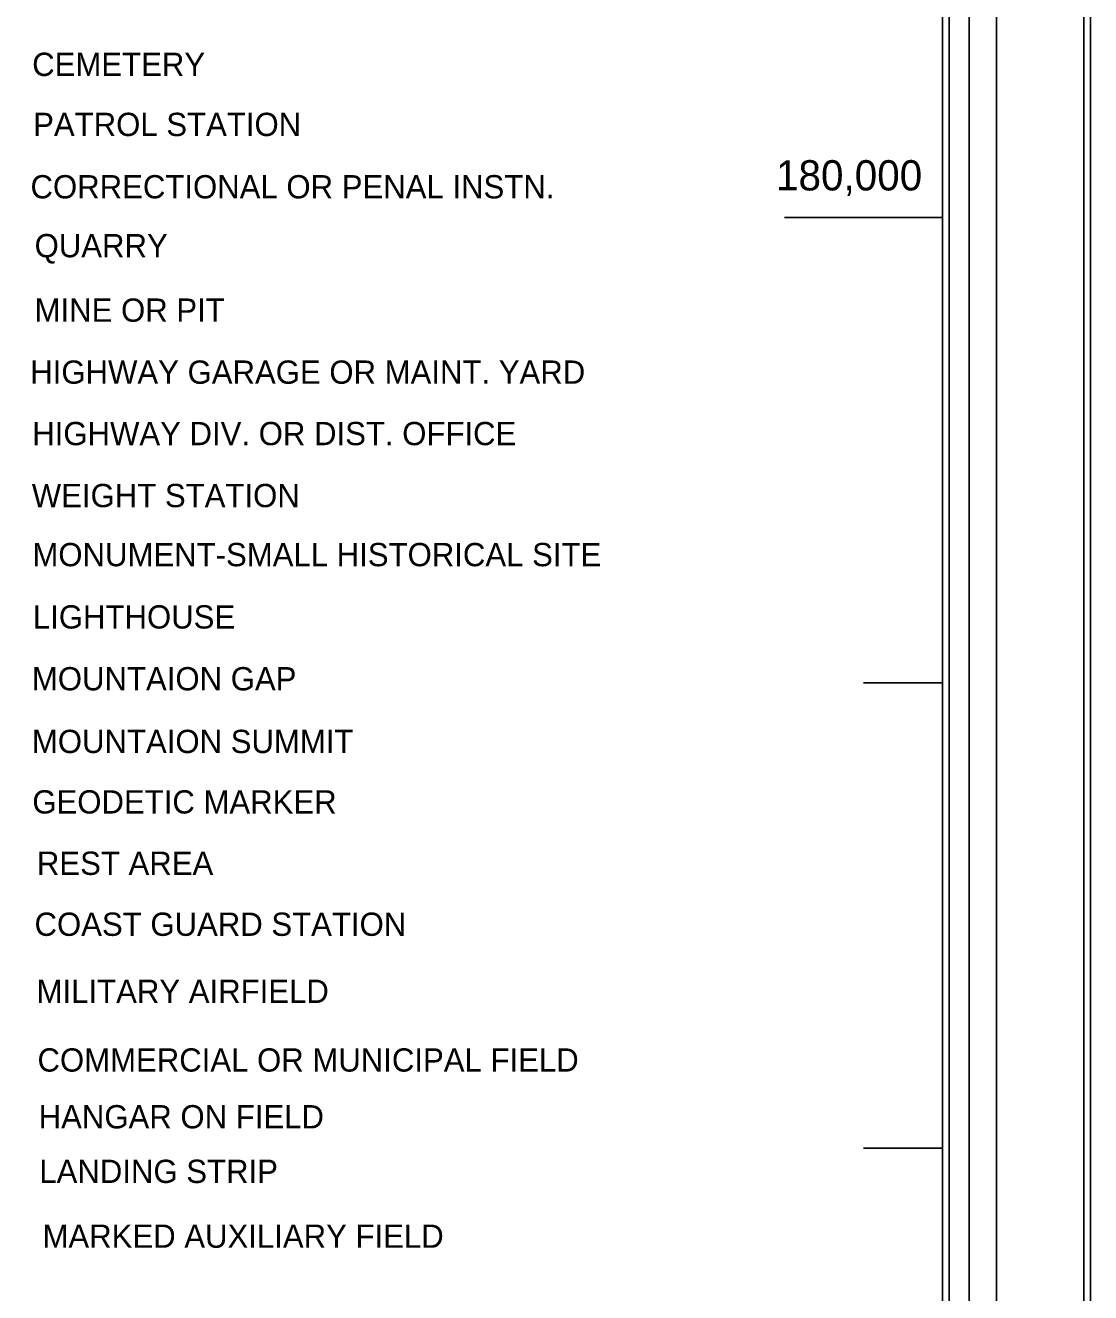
# Model space of a CAD drawing. Extents: x 5197761 to 5514561, y 1890130 to 2080942.
# Drawn here: x 5491672 to 5514561, y 1958318 to 1985551 of the extents above; entities that cross this region are included whole.
import ezdxf

# ---------------------------------------------------------------- set-up
doc = ezdxf.new("R2010")
doc.units = 0
for name, color, linetype in [('Exist Aviation Coast Guard Station Label', 7, 'Continuous'), ('Exist Aviation Commercial or Municipal Label', 7, 'Continuous'), ('Exist Aviation Field Marked Auxiliary Label', 7, 'Continuous'), ('Exist Aviation Hanger Label', 7, 'Continuous'), ('Exist Aviation Military Label', 7, 'Continuous'), ('Exist Aviation Public Landing Strip Label', 7, 'Continuous'), ('Exist Civil Correctional or Penal Institution Label', 7, 'Continuous'), ('Exist Civil NCDOT Division Office Label', 7, 'Continuous'), ('Exist Civil NCDOT Garage or Maintenance Office Label', 7, 'Continuous'), ('Exist Civil Patrol Station Label', 7, 'Continuous'), ('Exist Cultural Cemetery Label', 7, 'Continuous'), ('Exist Cultural Historical Site Label', 7, 'Continuous'), ('Exist Cultural Lighthouse Label', 7, 'Continuous'), ('Exist Cultural Weight Station Label', 7, 'Continuous'), ('Exist Geographical Mine Shaft Label', 7, 'Continuous'), ('Exist Geographical Mountain Gap Label', 7, 'Continuous'), ('Exist Geographical Mountain Summit Label', 7, 'Continuous'), ('Exist Geographical Quarry Label', 7, 'Continuous'), ('Exist Road Primary Interstate Rest Area Label', 7, 'Continuous'), ('Exist Survey Geodetic Marker Label', 7, 'Continuous'), ('Map Preparation Base StatePlane Tick Label', 7, 'Continuous'), ('Map Preparation Base StatePlane Tick Mark', 7, 'Continuous'), ('Map Preparation Border Antique Large Shape', 7, 'Continuous'), ('Map Preparation Border Antique Small Shape', 7, 'Continuous'), ('Map Preparation Border Black Inside Shape', 7, 'Continuous'), ('Map Preparation Border Black Middle Shape', 7, 'Continuous'), ('Map Preparation Border Black Outside Shape', 7, 'Continuous')]:
    doc.layers.add(name, color=color, linetype=linetype)

msp = doc.modelspace()

# ---------------------------------------------------------------- linework, layer by layer
at = {"layer": 'Map Preparation Base StatePlane Tick Mark'}
for p, q in [((5507980, 1981420), (5511378, 1981420)), ((5509679, 1971420), (5511378, 1971420)), ((5509679, 1961420), (5511378, 1961420))]:
    msp.add_line(p, q, dxfattribs=at)
at = {"layer": 'Map Preparation Border Antique Large Shape'}
msp.add_lwpolyline([(5197907, 2074783), (5207205, 2074783), (5207205, 1892697), (5512539, 1892697), (5512539, 2072359), (5207205, 2072359), (5207205, 2074783), (5514414, 2074783), (5514414, 1890276), (5197907, 1890276)], close=True, dxfattribs=at)
at = {"layer": 'Map Preparation Border Antique Small Shape'}
msp.add_lwpolyline([(5207791, 2071720), (5208220, 2071720), (5208220, 1893712), (5511524, 1893712), (5511524, 2071291), (5208220, 2071291), (5208220, 2071720), (5207791, 2071720), (5511953, 2071720), (5511953, 1893283), (5208220, 1893283), (5207791, 1893283)], close=True, dxfattribs=at)
at = {"layer": 'Map Preparation Border Black Inside Shape'}
msp.add_lwpolyline([(5208220, 2071291), (5511524, 2071291), (5511524, 1893712), (5208366, 1893712), (5208366, 1893858), (5511378, 1893858), (5511378, 2071145), (5208366, 2071145), (5208366, 1893858), (5208366, 1893712), (5208220, 1893712), (5208220, 1893858)], close=True, dxfattribs=at)
at = {"layer": 'Map Preparation Border Black Middle Shape'}
msp.add_lwpolyline([(5207205, 2072359), (5512539, 2072359), (5512539, 1892697), (5511953, 1892697), (5207791, 1892697), (5207791, 1893283), (5511953, 1893283), (5511953, 2071720), (5207791, 2071720), (5207791, 1892697), (5207205, 1892697)], close=True, dxfattribs=at)
at = {"layer": 'Map Preparation Border Black Outside Shape'}
msp.add_lwpolyline([(5197761, 2074930), (5514561, 2074930), (5514561, 1890130), (5197907, 1890130), (5197907, 1890276), (5514414, 1890276), (5514414, 2074783), (5197907, 2074783), (5197907, 1890130), (5197761, 1890130)], close=True, dxfattribs=at)

# ---------------------------------------------------------------- texts
at = {"layer": 'Exist Aviation Coast Guard Station Label'}
msp.add_text('COAST GUARD STATION', height=500, dxfattribs=at).set_placement((5491869, 1965985))
at = {"layer": 'Exist Aviation Commercial or Municipal Label'}
msp.add_text('COMMERCIAL OR MUNICIPAL FIELD', height=500, dxfattribs=at).set_placement((5491933, 1963068))
at = {"layer": 'Exist Aviation Field Marked Auxiliary Label'}
msp.add_text('MARKED AUXILIARY FIELD', height=500, dxfattribs=at).set_placement((5492041, 1959282))
at = {"layer": 'Exist Aviation Hanger Label'}
msp.add_text('HANGAR ON FIELD', height=500, dxfattribs=at).set_placement((5491958, 1961848))
at = {"layer": 'Exist Aviation Military Label'}
msp.add_text('MILITARY AIRFIELD', height=500, dxfattribs=at).set_placement((5491914, 1964544))
at = {"layer": 'Exist Aviation Public Landing Strip Label'}
msp.add_text('LANDING STRIP', height=500, dxfattribs=at).set_placement((5491972, 1960675))
at = {"layer": 'Exist Civil Correctional or Penal Institution Label'}
msp.add_text('CORRECTIONAL OR PENAL INSTN.', height=500, dxfattribs=at).set_placement((5491783, 1981832))
at = {"layer": 'Exist Civil NCDOT Division Office Label'}
msp.add_text('HIGHWAY DIV. OR DIST. OFFICE', height=500, dxfattribs=at).set_placement((5491820, 1976529))
at = {"layer": 'Exist Civil NCDOT Garage or Maintenance Office Label'}
msp.add_text('HIGHWAY GARAGE OR MAINT. YARD', height=500, dxfattribs=at).set_placement((5491777, 1977849))
at = {"layer": 'Exist Civil Patrol Station Label'}
msp.add_text('PATROL STATION', height=500, dxfattribs=at).set_placement((5491840, 1983172))
at = {"layer": 'Exist Cultural Cemetery Label'}
msp.add_text('CEMETERY', height=500, dxfattribs=at).set_placement((5491819, 1984463))
at = {"layer": 'Exist Cultural Historical Site Label'}
msp.add_text('MONUMENT-SMALL HISTORICAL SITE', height=500, dxfattribs=at).set_placement((5491824, 1973928))
at = {"layer": 'Exist Cultural Lighthouse Label'}
msp.add_text('LIGHTHOUSE', height=500, dxfattribs=at).set_placement((5491834, 1972589))
at = {"layer": 'Exist Cultural Weight Station Label'}
msp.add_text('WEIGHT STATION', height=500, dxfattribs=at).set_placement((5491811, 1975197))
at = {"layer": 'Exist Geographical Mine Shaft Label'}
msp.add_text('MINE OR PIT', height=500, dxfattribs=at).set_placement((5491871, 1979181))
at = {"layer": 'Exist Geographical Mountain Gap Label'}
msp.add_text('MOUNTAION GAP', height=500, dxfattribs=at).set_placement((5491813, 1971260))
at = {"layer": 'Exist Geographical Mountain Summit Label'}
msp.add_text('MOUNTAION SUMMIT', height=500, dxfattribs=at).set_placement((5491813, 1969913))
at = {"layer": 'Exist Geographical Quarry Label'}
msp.add_text('QUARRY', height=500, dxfattribs=at).set_placement((5491871, 1980567))
at = {"layer": 'Exist Road Primary Interstate Rest Area Label'}
msp.add_text('REST AREA', height=500, dxfattribs=at).set_placement((5491920, 1967295))
at = {"layer": 'Exist Survey Geodetic Marker Label'}
msp.add_text('GEODETIC MARKER', height=500, dxfattribs=at).set_placement((5491822, 1968614))
at = {"layer": 'Map Preparation Base StatePlane Tick Label'}
msp.add_text('180,000', height=650, dxfattribs=at).set_placement((5507800, 1982003))

doc.saveas('drawing.dxf')
